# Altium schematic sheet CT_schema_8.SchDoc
size 277 x 170 mm
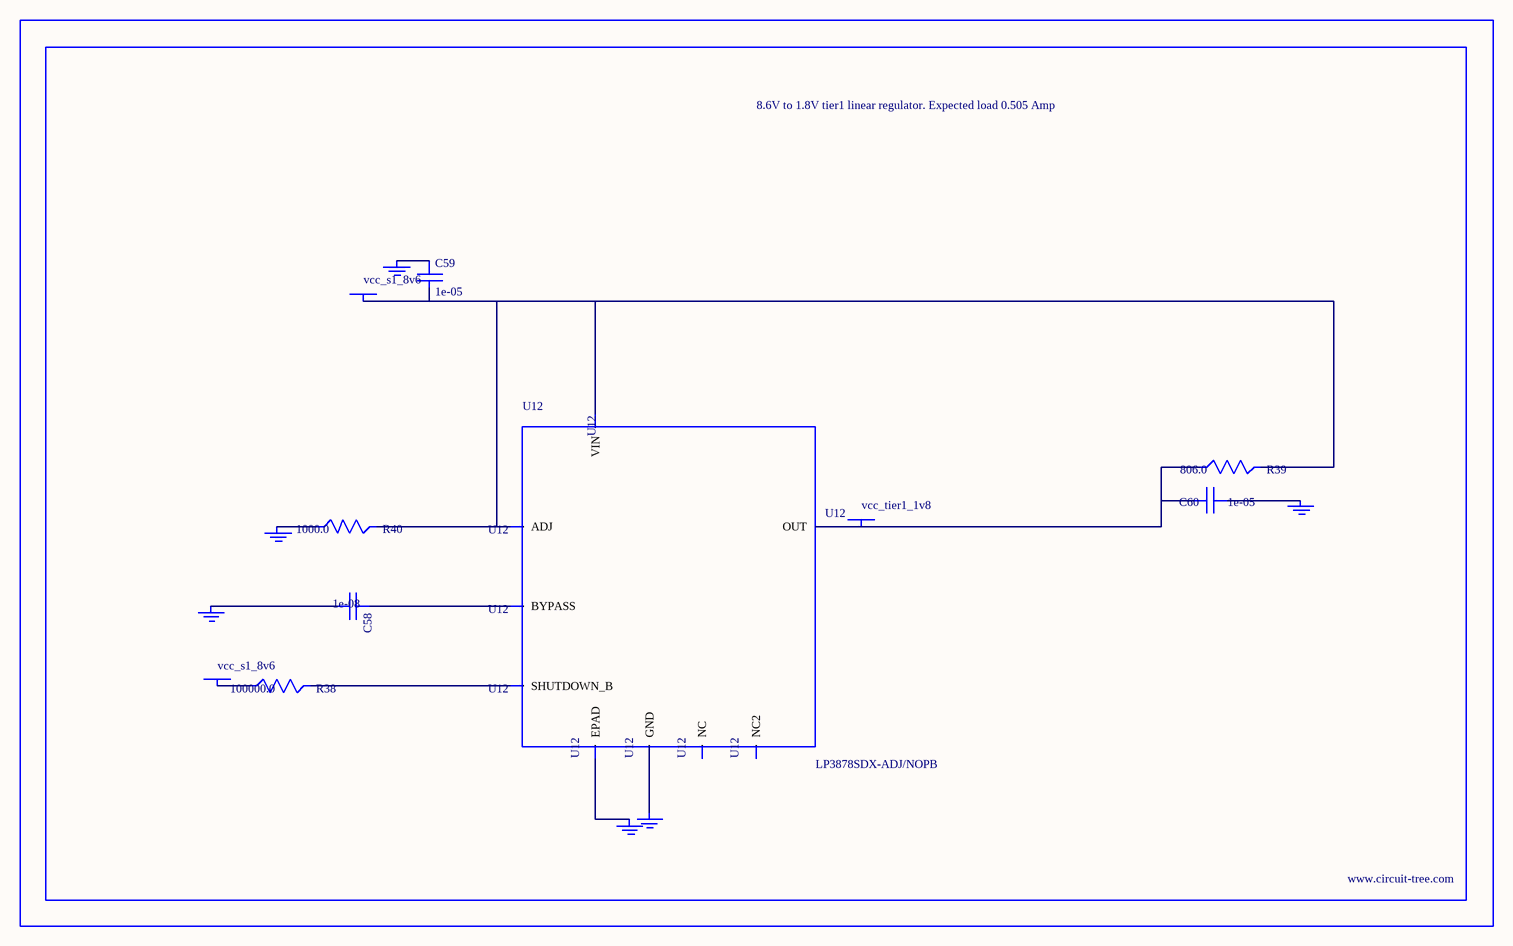
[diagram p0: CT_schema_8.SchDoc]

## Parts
BORDER7  (no value)
C58  1e-08  [C0402]
C59  1e-05  [C1206]
C60  1e-05  [C0805]
GND_INSTANCE_7_0  (no value)
GND_INSTANCE_7_1  (no value)
GND_INSTANCE_7_2  (no value)
GND_INSTANCE_7_3  (no value)
GND_INSTANCE_7_4  (no value)
GND_INSTANCE_7_5  (no value)
POWER_INSTANCE_7_0  vcc_s1_8v6
POWER_INSTANCE_7_1  vcc_s1_8v6
POWER_INSTANCE_7_2  vcc_tier1_1v8
R38  100000.0  [R0603]
R39  806.0  [R0603]
R40  1000.0  [R0603]
U12  LP3878SDX-ADJ/NOPB  [WSON-8]

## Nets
NetC58_1: C58.1 U12.1(BYPASS)
NetC58_2: C58.2 GND_INSTANCE_7_0.0(GND)
NetC59_1: C59.1 GND_INSTANCE_7_1.0(GND)
NetC59_2: C59.2 POWER_INSTANCE_7_0.0(PWR) R39.2 R40.2 U12.4(VIN) U12.6(ADJ)
NetC60_1: C60.1 GND_INSTANCE_7_2.0(GND)
NetC60_2: C60.2 POWER_INSTANCE_7_2.0(PWR) R39.1 U12.5(OUT)
NetGND_INSTANCE_7_3_0: GND_INSTANCE_7_3.0(GND) R40.1
NetGND_INSTANCE_7_4_0: GND_INSTANCE_7_4.0(GND) U12.PAD(EPAD)
NetGND_INSTANCE_7_5_0: GND_INSTANCE_7_5.0(GND) U12.3(GND)
NetPOWER_INSTANCE_7_1_0: POWER_INSTANCE_7_1.0(PWR) R38.1
NetR38_2: R38.2 U12.8(SHUTDOWN_B)

Not connected (* = marked no-connect by the designer): U12 2(NC) 7(NC2)

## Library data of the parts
BORDER7 = BORDER_PAGE7
C58 = C0402C103K3RAC
C59 = C1206C106K3RACTU
C60 = GRM219R60J106ME19D
GND_INSTANCE_7_0-GND_INSTANCE_7_5 = GND
POWER_INSTANCE_7_0-POWER_INSTANCE_7_2 = PWR
R38 = RC0603JR-07100KL
R39 = ERJ-3EKF8060V
R40 = RC0603JR-071KL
